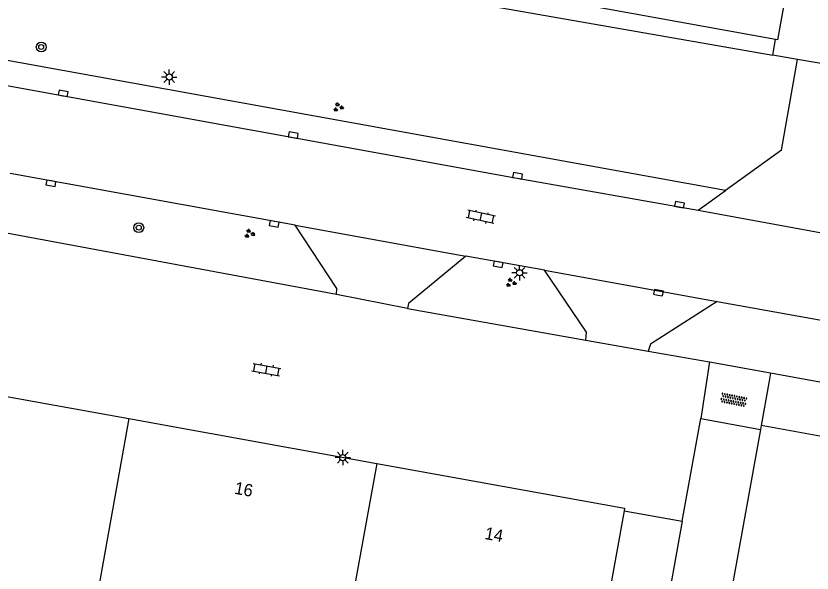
# Model space of a CAD drawing. Extents: x 130998 to 133001, y 398999 to 403002.
# Drawn here: x 132398.9 to 132463.8, y 399206.6 to 399252 of the extents above; entities that cross this region are included whole.
import ezdxf

# ---------------------------------------------------------------- set-up
doc = ezdxf.new("R2010")
doc.units = 0
for name, color, linetype in [('gg-afsc-hekwerk', 7, 'Continuous'), ('gg-anno-huisnummerreeks BGT', 7, 'Continuous'), ('gg-bbg-hoofdgebouw', 7, 'Continuous'), ('gg-bbg-tussenscheiding', 7, 'Continuous'), ('gg-knt-verharding', 7, 'Continuous'), ('gg-knt-verharding nz', 7, 'Continuous'), ('gt-symb-boom', 7, 'Continuous'), ('gt-symb-groenvak', 7, 'Continuous'), ('gt-symb-klinker verharding', 7, 'Continuous'), ('gt-symb-kolk', 7, 'Continuous'), ('gt-symb-lichtmast', 7, 'Continuous'), ('gt-symb-overige verharding', 7, 'Continuous')]:
    doc.layers.add(name, color=color, linetype=linetype)

# ---------------------------------------------------------------- blocks, each defined once
blk = doc.blocks.new('gt0-KOLK')
at = {"layer": 'gt-symb-kolk'}
blk.add_lwpolyline([(0, 0), (0.375, 0), (0.375, 0.4), (-0.375, 0.4), (-0.375, 0), (0, 0)], dxfattribs=at)
blk = doc.blocks.new('gt0-OVH')
at = {"layer": 'gt-symb-overige verharding'}
for points in [[(-0.972, 0.298), (-0.967, 0.308), (-0.965, 0.319), (-0.966, 0.33), (-0.971, 0.34), (-0.978, 0.348), (-0.988, 0.353), (-0.999, 0.355), (-1.01, 0.354), (-1.02, 0.349), (-1.028, 0.342), (-1.033, 0.332), (-1.035, 0.321), (-1.034, 0.31), (-1.029, 0.3), (-1.022, 0.292), (-1.012, 0.287), (-1.001, 0.285), (-0.99, 0.286), (-0.98, 0.291)], [(-0.872, 0.106), (-0.867, 0.116), (-0.865, 0.126), (-0.866, 0.137), (-0.871, 0.147), (-0.878, 0.156), (-0.888, 0.161), (-0.899, 0.163), (-0.91, 0.162), (-0.92, 0.157), (-0.928, 0.15), (-0.933, 0.14), (-0.935, 0.129), (-0.934, 0.118), (-0.929, 0.108), (-0.922, 0.1), (-0.912, 0.095), (-0.901, 0.092), (-0.89, 0.094), (-0.88, 0.098)], [(-0.772, 0.298), (-0.767, 0.308), (-0.765, 0.319), (-0.766, 0.33), (-0.771, 0.34), (-0.778, 0.348), (-0.788, 0.353), (-0.799, 0.355), (-0.81, 0.354), (-0.82, 0.349), (-0.828, 0.342), (-0.833, 0.332), (-0.835, 0.321), (-0.834, 0.31), (-0.829, 0.3), (-0.822, 0.292), (-0.812, 0.287), (-0.801, 0.285), (-0.79, 0.286), (-0.78, 0.291)], [(-0.672, 0.106), (-0.667, 0.116), (-0.665, 0.126), (-0.666, 0.137), (-0.671, 0.147), (-0.678, 0.156), (-0.688, 0.161), (-0.699, 0.163), (-0.71, 0.162), (-0.72, 0.157), (-0.728, 0.15), (-0.733, 0.14), (-0.735, 0.129), (-0.734, 0.118), (-0.729, 0.108), (-0.722, 0.1), (-0.712, 0.095), (-0.701, 0.092), (-0.69, 0.094), (-0.68, 0.098)], [(-0.572, 0.298), (-0.567, 0.308), (-0.565, 0.319), (-0.566, 0.33), (-0.571, 0.34), (-0.578, 0.348), (-0.588, 0.353), (-0.599, 0.355), (-0.61, 0.354), (-0.62, 0.349), (-0.628, 0.342), (-0.633, 0.332), (-0.635, 0.321), (-0.634, 0.31), (-0.629, 0.3), (-0.622, 0.292), (-0.612, 0.287), (-0.601, 0.285), (-0.59, 0.286), (-0.58, 0.291)], [(-0.472, 0.106), (-0.467, 0.116), (-0.465, 0.126), (-0.466, 0.137), (-0.471, 0.147), (-0.478, 0.156), (-0.488, 0.161), (-0.499, 0.163), (-0.51, 0.162), (-0.52, 0.157), (-0.528, 0.15), (-0.533, 0.14), (-0.535, 0.129), (-0.534, 0.118), (-0.529, 0.108), (-0.522, 0.1), (-0.512, 0.095), (-0.501, 0.092), (-0.49, 0.094), (-0.48, 0.098)], [(-0.372, 0.298), (-0.367, 0.308), (-0.365, 0.319), (-0.366, 0.33), (-0.371, 0.34), (-0.378, 0.348), (-0.388, 0.353), (-0.399, 0.355), (-0.41, 0.354), (-0.42, 0.349), (-0.428, 0.342), (-0.433, 0.332), (-0.435, 0.321), (-0.434, 0.31), (-0.429, 0.3), (-0.422, 0.292), (-0.412, 0.287), (-0.401, 0.285), (-0.39, 0.286), (-0.38, 0.291)], [(-0.272, 0.106), (-0.267, 0.116), (-0.265, 0.126), (-0.266, 0.137), (-0.271, 0.147), (-0.278, 0.156), (-0.288, 0.161), (-0.299, 0.163), (-0.31, 0.162), (-0.32, 0.157), (-0.328, 0.15), (-0.333, 0.14), (-0.335, 0.129), (-0.334, 0.118), (-0.329, 0.108), (-0.322, 0.1), (-0.312, 0.095), (-0.301, 0.092), (-0.29, 0.094), (-0.28, 0.098)], [(-0.172, 0.298), (-0.167, 0.308), (-0.165, 0.319), (-0.166, 0.33), (-0.171, 0.34), (-0.178, 0.348), (-0.188, 0.353), (-0.199, 0.355), (-0.21, 0.354), (-0.22, 0.349), (-0.228, 0.342), (-0.233, 0.332), (-0.235, 0.321), (-0.234, 0.31), (-0.229, 0.3), (-0.222, 0.292), (-0.212, 0.287), (-0.201, 0.285), (-0.19, 0.286), (-0.18, 0.291)], [(-0.072, 0.106), (-0.067, 0.116), (-0.065, 0.126), (-0.066, 0.137), (-0.071, 0.147), (-0.078, 0.156), (-0.088, 0.161), (-0.099, 0.163), (-0.11, 0.162), (-0.12, 0.157), (-0.128, 0.15), (-0.133, 0.14), (-0.135, 0.129), (-0.134, 0.118), (-0.129, 0.108), (-0.122, 0.1), (-0.112, 0.095), (-0.101, 0.092), (-0.09, 0.094), (-0.08, 0.098)], [(0.028, 0.298), (0.033, 0.308), (0.035, 0.319), (0.034, 0.33), (0.029, 0.34), (0.022, 0.348), (0.012, 0.353), (0.001, 0.355), (-0.01, 0.354), (-0.02, 0.349), (-0.028, 0.342), (-0.033, 0.332), (-0.035, 0.321), (-0.034, 0.31), (-0.029, 0.3), (-0.022, 0.292), (-0.012, 0.287), (-0.001, 0.285), (0.01, 0.286), (0.02, 0.291)], [(0.128, 0.106), (0.133, 0.116), (0.135, 0.126), (0.134, 0.137), (0.129, 0.147), (0.122, 0.156), (0.112, 0.161), (0.101, 0.163), (0.09, 0.162), (0.08, 0.157), (0.072, 0.15), (0.067, 0.14), (0.065, 0.129), (0.066, 0.118), (0.071, 0.108), (0.078, 0.1), (0.088, 0.095), (0.099, 0.092), (0.11, 0.094), (0.12, 0.098)], [(0.228, 0.298), (0.233, 0.308), (0.235, 0.319), (0.234, 0.33), (0.229, 0.34), (0.222, 0.348), (0.212, 0.353), (0.201, 0.355), (0.19, 0.354), (0.18, 0.349), (0.172, 0.342), (0.167, 0.332), (0.165, 0.321), (0.166, 0.31), (0.171, 0.3), (0.178, 0.292), (0.188, 0.287), (0.199, 0.285), (0.21, 0.286), (0.22, 0.291)], [(0.328, 0.106), (0.333, 0.116), (0.335, 0.126), (0.334, 0.137), (0.329, 0.147), (0.322, 0.156), (0.312, 0.161), (0.301, 0.163), (0.29, 0.162), (0.28, 0.157), (0.272, 0.15), (0.267, 0.14), (0.265, 0.129), (0.266, 0.118), (0.271, 0.108), (0.278, 0.1), (0.288, 0.095), (0.299, 0.092), (0.31, 0.094), (0.32, 0.098)], [(0.428, 0.298), (0.433, 0.308), (0.435, 0.319), (0.434, 0.33), (0.429, 0.34), (0.422, 0.348), (0.412, 0.353), (0.401, 0.355), (0.39, 0.354), (0.38, 0.349), (0.372, 0.342), (0.367, 0.332), (0.365, 0.321), (0.366, 0.31), (0.371, 0.3), (0.378, 0.292), (0.388, 0.287), (0.399, 0.285), (0.41, 0.286), (0.42, 0.291)], [(0.528, 0.106), (0.533, 0.116), (0.535, 0.126), (0.534, 0.137), (0.529, 0.147), (0.522, 0.156), (0.512, 0.161), (0.501, 0.163), (0.49, 0.162), (0.48, 0.157), (0.472, 0.15), (0.467, 0.14), (0.465, 0.129), (0.466, 0.118), (0.471, 0.108), (0.478, 0.1), (0.488, 0.095), (0.499, 0.092), (0.51, 0.094), (0.52, 0.098)], [(0.628, 0.298), (0.633, 0.308), (0.635, 0.319), (0.634, 0.33), (0.629, 0.34), (0.622, 0.348), (0.612, 0.353), (0.601, 0.355), (0.59, 0.354), (0.58, 0.349), (0.572, 0.342), (0.567, 0.332), (0.565, 0.321), (0.566, 0.31), (0.571, 0.3), (0.578, 0.292), (0.588, 0.287), (0.599, 0.285), (0.61, 0.286), (0.62, 0.291)], [(0.728, 0.106), (0.733, 0.116), (0.735, 0.126), (0.734, 0.137), (0.729, 0.147), (0.722, 0.156), (0.712, 0.161), (0.701, 0.163), (0.69, 0.162), (0.68, 0.157), (0.672, 0.15), (0.667, 0.14), (0.665, 0.129), (0.666, 0.118), (0.671, 0.108), (0.678, 0.1), (0.688, 0.095), (0.699, 0.092), (0.71, 0.094), (0.72, 0.098)], [(0.828, 0.298), (0.833, 0.308), (0.835, 0.319), (0.834, 0.33), (0.829, 0.34), (0.822, 0.348), (0.812, 0.353), (0.801, 0.355), (0.79, 0.354), (0.78, 0.349), (0.772, 0.342), (0.767, 0.332), (0.765, 0.321), (0.766, 0.31), (0.771, 0.3), (0.778, 0.292), (0.788, 0.287), (0.799, 0.285), (0.81, 0.286), (0.82, 0.291)], [(0.928, 0.106), (0.933, 0.116), (0.935, 0.126), (0.934, 0.137), (0.929, 0.147), (0.922, 0.156), (0.912, 0.161), (0.901, 0.163), (0.89, 0.162), (0.88, 0.157), (0.872, 0.15), (0.867, 0.14), (0.865, 0.129), (0.866, 0.118), (0.871, 0.108), (0.878, 0.1), (0.888, 0.095), (0.899, 0.092), (0.91, 0.094), (0.92, 0.098)], [(1.028, 0.298), (1.033, 0.308), (1.035, 0.319), (1.034, 0.33), (1.029, 0.34), (1.022, 0.348), (1.012, 0.353), (1.001, 0.355), (0.99, 0.354), (0.98, 0.349), (0.972, 0.342), (0.967, 0.332), (0.965, 0.321), (0.966, 0.31), (0.971, 0.3), (0.978, 0.292), (0.988, 0.287), (0.999, 0.285), (1.01, 0.286), (1.02, 0.291)], [(-0.972, -0.142), (-0.967, -0.132), (-0.965, -0.121), (-0.966, -0.11), (-0.971, -0.1), (-0.978, -0.092), (-0.988, -0.087), (-0.999, -0.085), (-1.01, -0.086), (-1.02, -0.091), (-1.028, -0.098), (-1.033, -0.108), (-1.035, -0.119), (-1.034, -0.13), (-1.029, -0.14), (-1.022, -0.148), (-1.012, -0.153), (-1.001, -0.155), (-0.99, -0.154), (-0.98, -0.149)], [(-0.872, -0.334), (-0.867, -0.324), (-0.865, -0.314), (-0.866, -0.303), (-0.871, -0.293), (-0.878, -0.284), (-0.888, -0.279), (-0.899, -0.277), (-0.91, -0.278), (-0.92, -0.283), (-0.928, -0.29), (-0.933, -0.3), (-0.935, -0.311), (-0.934, -0.322), (-0.929, -0.332), (-0.922, -0.34), (-0.912, -0.345), (-0.901, -0.348), (-0.89, -0.346), (-0.88, -0.342)], [(-0.772, -0.142), (-0.767, -0.132), (-0.765, -0.121), (-0.766, -0.11), (-0.771, -0.1), (-0.778, -0.092), (-0.788, -0.087), (-0.799, -0.085), (-0.81, -0.086), (-0.82, -0.091), (-0.828, -0.098), (-0.833, -0.108), (-0.835, -0.119), (-0.834, -0.13), (-0.829, -0.14), (-0.822, -0.148), (-0.812, -0.153), (-0.801, -0.155), (-0.79, -0.154), (-0.78, -0.149)], [(-0.672, -0.334), (-0.667, -0.324), (-0.665, -0.314), (-0.666, -0.303), (-0.671, -0.293), (-0.678, -0.284), (-0.688, -0.279), (-0.699, -0.277), (-0.71, -0.278), (-0.72, -0.283), (-0.728, -0.29), (-0.733, -0.3), (-0.735, -0.311), (-0.734, -0.322), (-0.729, -0.332), (-0.722, -0.34), (-0.712, -0.345), (-0.701, -0.348), (-0.69, -0.346), (-0.68, -0.342)], [(-0.572, -0.142), (-0.567, -0.132), (-0.565, -0.121), (-0.566, -0.11), (-0.571, -0.1), (-0.578, -0.092), (-0.588, -0.087), (-0.599, -0.085), (-0.61, -0.086), (-0.62, -0.091), (-0.628, -0.098), (-0.633, -0.108), (-0.635, -0.119), (-0.634, -0.13), (-0.629, -0.14), (-0.622, -0.148), (-0.612, -0.153), (-0.601, -0.155), (-0.59, -0.154), (-0.58, -0.149)], [(-0.472, -0.334), (-0.467, -0.324), (-0.465, -0.314), (-0.466, -0.303), (-0.471, -0.293), (-0.478, -0.284), (-0.488, -0.279), (-0.499, -0.277), (-0.51, -0.278), (-0.52, -0.283), (-0.528, -0.29), (-0.533, -0.3), (-0.535, -0.311), (-0.534, -0.322), (-0.529, -0.332), (-0.522, -0.34), (-0.512, -0.345), (-0.501, -0.348), (-0.49, -0.346), (-0.48, -0.342)], [(-0.372, -0.142), (-0.367, -0.132), (-0.365, -0.121), (-0.366, -0.11), (-0.371, -0.1), (-0.378, -0.092), (-0.388, -0.087), (-0.399, -0.085), (-0.41, -0.086), (-0.42, -0.091), (-0.428, -0.098), (-0.433, -0.108), (-0.435, -0.119), (-0.434, -0.13), (-0.429, -0.14), (-0.422, -0.148), (-0.412, -0.153), (-0.401, -0.155), (-0.39, -0.154), (-0.38, -0.149)], [(-0.272, -0.334), (-0.267, -0.324), (-0.265, -0.314), (-0.266, -0.303), (-0.271, -0.293), (-0.278, -0.284), (-0.288, -0.279), (-0.299, -0.277), (-0.31, -0.278), (-0.32, -0.283), (-0.328, -0.29), (-0.333, -0.3), (-0.335, -0.311), (-0.334, -0.322), (-0.329, -0.332), (-0.322, -0.34), (-0.312, -0.345), (-0.301, -0.348), (-0.29, -0.346), (-0.28, -0.342)], [(-0.172, -0.142), (-0.167, -0.132), (-0.165, -0.121), (-0.166, -0.11), (-0.171, -0.1), (-0.178, -0.092), (-0.188, -0.087), (-0.199, -0.085), (-0.21, -0.086), (-0.22, -0.091), (-0.228, -0.098), (-0.233, -0.108), (-0.235, -0.119), (-0.234, -0.13), (-0.229, -0.14), (-0.222, -0.148), (-0.212, -0.153), (-0.201, -0.155), (-0.19, -0.154), (-0.18, -0.149)], [(-0.072, -0.334), (-0.067, -0.324), (-0.065, -0.314), (-0.066, -0.303), (-0.071, -0.293), (-0.078, -0.284), (-0.088, -0.279), (-0.099, -0.277), (-0.11, -0.278), (-0.12, -0.283), (-0.128, -0.29), (-0.133, -0.3), (-0.135, -0.311), (-0.134, -0.322), (-0.129, -0.332), (-0.122, -0.34), (-0.112, -0.345), (-0.101, -0.348), (-0.09, -0.346), (-0.08, -0.342)], [(0.028, -0.142), (0.033, -0.132), (0.035, -0.121), (0.034, -0.11), (0.029, -0.1), (0.022, -0.092), (0.012, -0.087), (0.001, -0.085), (-0.01, -0.086), (-0.02, -0.091), (-0.028, -0.098), (-0.033, -0.108), (-0.035, -0.119), (-0.034, -0.13), (-0.029, -0.14), (-0.022, -0.148), (-0.012, -0.153), (-0.001, -0.155), (0.01, -0.154), (0.02, -0.149)], [(0.128, -0.334), (0.133, -0.324), (0.135, -0.314), (0.134, -0.303), (0.129, -0.293), (0.122, -0.284), (0.112, -0.279), (0.101, -0.277), (0.09, -0.278), (0.08, -0.283), (0.072, -0.29), (0.067, -0.3), (0.065, -0.311), (0.066, -0.322), (0.071, -0.332), (0.078, -0.34), (0.088, -0.345), (0.099, -0.348), (0.11, -0.346), (0.12, -0.342)], [(0.228, -0.142), (0.233, -0.132), (0.235, -0.121), (0.234, -0.11), (0.229, -0.1), (0.222, -0.092), (0.212, -0.087), (0.201, -0.085), (0.19, -0.086), (0.18, -0.091), (0.172, -0.098), (0.167, -0.108), (0.165, -0.119), (0.166, -0.13), (0.171, -0.14), (0.178, -0.148), (0.188, -0.153), (0.199, -0.155), (0.21, -0.154), (0.22, -0.149)], [(0.328, -0.334), (0.333, -0.324), (0.335, -0.314), (0.334, -0.303), (0.329, -0.293), (0.322, -0.284), (0.312, -0.279), (0.301, -0.277), (0.29, -0.278), (0.28, -0.283), (0.272, -0.29), (0.267, -0.3), (0.265, -0.311), (0.266, -0.322), (0.271, -0.332), (0.278, -0.34), (0.288, -0.345), (0.299, -0.348), (0.31, -0.346), (0.32, -0.342)], [(0.428, -0.142), (0.433, -0.132), (0.435, -0.121), (0.434, -0.11), (0.429, -0.1), (0.422, -0.092), (0.412, -0.087), (0.401, -0.085), (0.39, -0.086), (0.38, -0.091), (0.372, -0.098), (0.367, -0.108), (0.365, -0.119), (0.366, -0.13), (0.371, -0.14), (0.378, -0.148), (0.388, -0.153), (0.399, -0.155), (0.41, -0.154), (0.42, -0.149)], [(0.528, -0.334), (0.533, -0.324), (0.535, -0.314), (0.534, -0.303), (0.529, -0.293), (0.522, -0.284), (0.512, -0.279), (0.501, -0.277), (0.49, -0.278), (0.48, -0.283), (0.472, -0.29), (0.467, -0.3), (0.465, -0.311), (0.466, -0.322), (0.471, -0.332), (0.478, -0.34), (0.488, -0.345), (0.499, -0.348), (0.51, -0.346), (0.52, -0.342)], [(0.628, -0.142), (0.633, -0.132), (0.635, -0.121), (0.634, -0.11), (0.629, -0.1), (0.622, -0.092), (0.612, -0.087), (0.601, -0.085), (0.59, -0.086), (0.58, -0.091), (0.572, -0.098), (0.567, -0.108), (0.565, -0.119), (0.566, -0.13), (0.571, -0.14), (0.578, -0.148), (0.588, -0.153), (0.599, -0.155), (0.61, -0.154), (0.62, -0.149)], [(0.728, -0.334), (0.733, -0.324), (0.735, -0.314), (0.734, -0.303), (0.729, -0.293), (0.722, -0.284), (0.712, -0.279), (0.701, -0.277), (0.69, -0.278), (0.68, -0.283), (0.672, -0.29), (0.667, -0.3), (0.665, -0.311), (0.666, -0.322), (0.671, -0.332), (0.678, -0.34), (0.688, -0.345), (0.699, -0.348), (0.71, -0.346), (0.72, -0.342)], [(0.828, -0.142), (0.833, -0.132), (0.835, -0.121), (0.834, -0.11), (0.829, -0.1), (0.822, -0.092), (0.812, -0.087), (0.801, -0.085), (0.79, -0.086), (0.78, -0.091), (0.772, -0.098), (0.767, -0.108), (0.765, -0.119), (0.766, -0.13), (0.771, -0.14), (0.778, -0.148), (0.788, -0.153), (0.799, -0.155), (0.81, -0.154), (0.82, -0.149)], [(0.928, -0.334), (0.933, -0.324), (0.935, -0.314), (0.934, -0.303), (0.929, -0.293), (0.922, -0.284), (0.912, -0.279), (0.901, -0.277), (0.89, -0.278), (0.88, -0.283), (0.872, -0.29), (0.867, -0.3), (0.865, -0.311), (0.866, -0.322), (0.871, -0.332), (0.878, -0.34), (0.888, -0.345), (0.899, -0.348), (0.91, -0.346), (0.92, -0.342)], [(1.028, -0.142), (1.033, -0.132), (1.035, -0.121), (1.034, -0.11), (1.029, -0.1), (1.022, -0.092), (1.012, -0.087), (1.001, -0.085), (0.99, -0.086), (0.98, -0.091), (0.972, -0.098), (0.967, -0.108), (0.965, -0.119), (0.966, -0.13), (0.971, -0.14), (0.978, -0.148), (0.988, -0.153), (0.999, -0.155), (1.01, -0.154), (1.02, -0.149)]]:
    blk.add_lwpolyline(points, close=True, dxfattribs=at)
blk = doc.blocks.new('gt0-BOOM')
at = {"layer": 'gt-symb-boom'}
for radius in [0.4, 0.2]:
    blk.add_circle((0, 0), radius, dxfattribs=at)
blk = doc.blocks.new('gt0-LMAST')
at = {"layer": 'gt-symb-lichtmast'}
for p, q in [((-0.182, 0.173), (-0.447, 0.438)), ((-0.005, 0.246), (-0.005, 0.621)), ((0.172, 0.173), (0.437, 0.438)), ((-0.255, -0.004), (-0.63, -0.004)), ((-0.182, -0.181), (-0.447, -0.446)), ((-0.005, -0.254), (-0.005, -0.629)), ((0.437, -0.446), (0.172, -0.181)), ((0.245, -0.004), (0.62, -0.004))]:
    blk.add_line(p, q, dxfattribs=at)
blk.add_circle((-0.005, -0.004), 0.25, dxfattribs=at)
blk = doc.blocks.new('gt0-GRVAK')
at = {"layer": 'gt-symb-groenvak'}
for p, q in [((-0.11, 0.189), (-0.228, 0.24)), ((-0.182, 0.153), (0.088, 0.153)), ((-0.091, 0.211), (-0.156, 0.322)), ((-0.047, 0.214), (-0.047, 0.393)), ((-0.004, 0.211), (0.061, 0.322)), ((0.015, 0.189), (0.133, 0.24)), ((0.262, -0.052), (0.197, 0.059)), ((0.305, -0.049), (0.305, 0.13)), ((0.349, -0.052), (0.414, 0.059)), ((-0.245, -0.228), (-0.363, -0.177)), ((-0.318, -0.264), (-0.047, -0.264)), ((-0.226, -0.206), (-0.291, -0.095)), ((-0.183, -0.203), (-0.183, -0.024)), ((-0.139, -0.206), (-0.074, -0.095)), ((-0.12, -0.228), (-0.002, -0.177)), ((0.243, -0.074), (0.125, -0.023)), ((0.17, -0.11), (0.441, -0.11)), ((0.368, -0.074), (0.486, -0.023))]:
    blk.add_line(p, q, dxfattribs=at)
blk = doc.blocks.new('gt0-KL1')
at = {"layer": 'gt-symb-klinker verharding'}
for p, q in [((-1.15, 0.3), (1.15, 0.3)), ((-1, -0.3), (-1, 0.3)), ((-0.5, 0.3), (-0.5, 0.45)), ((0, -0.3), (0, 0.3)), ((0.5, 0.3), (0.5, 0.45)), ((1, -0.3), (1, 0.3)), ((-1.15, -0.3), (1.15, -0.3)), ((-0.5, -0.45), (-0.5, -0.3)), ((0.5, -0.45), (0.5, -0.3))]:
    blk.add_line(p, q, dxfattribs=at)

msp = doc.modelspace()

# ---------------------------------------------------------------- linework, layer by layer
at = {"layer": 'gg-afsc-hekwerk'}
for p, q in [((132460.601, 399248.82), (132460.809, 399250.107)), ((132462.598, 399248.474), (132460.601, 399248.82)), ((132468.473, 399247.458), (132462.598, 399248.474)), ((132455.426, 399223.831), (132454.727, 399219.227)), ((132453.207, 399210.854), (132454.727, 399219.227)), ((132454.727, 399219.227), (132459.591, 399218.314)), ((132448.481, 399211.712), (132453.207, 399210.854)), ((132453.207, 399210.854), (132451.577, 399201.878))]:
    msp.add_line(p, q, dxfattribs=at)
at = {"layer": 'gg-bbg-hoofdgebouw'}
for p, q in [((132387.901, 399222.87), (132408.103, 399219.217)), ((132408.103, 399219.217), (132428.306, 399215.564)), ((132459.591, 399218.314), (132453.594, 399185.159)), ((132459.65, 399218.642), (132459.591, 399218.314)), ((132514.6, 399208.747), (132459.65, 399218.642)), ((132428.306, 399215.564), (132448.517, 399211.909)), ((132448.481, 399211.712), (132444.01, 399186.885)), ((132448.517, 399211.909), (132448.481, 399211.712))]:
    msp.add_line(p, q, dxfattribs=at)
for points in [[(132413.478, 399310.379), (132413.991, 399313.232), (132414.422, 399315.091), (132470.77, 399304.908), (132470.429, 399303.025), (132470.54, 399303.004), (132460.978, 399250.076), (132460.809, 399250.107)], [(132460.809, 399250.107), (132404.38, 399260.315), (132404.401, 399260.417)]]:
    msp.add_lwpolyline(points, dxfattribs=at)
at = {"layer": 'gg-bbg-tussenscheiding'}
for p, q in [((132408.103, 399219.217), (132399.369, 399170.915)), ((132428.306, 399215.564), (132419.572, 399167.262))]:
    msp.add_line(p, q, dxfattribs=at)
at = {"layer": 'gg-knt-verharding'}
for p, q in [((132404.069, 399258.766), (132460.601, 399248.82)), ((132461.308, 399241.073), (132462.598, 399248.474)), ((132461.308, 399241.073), (132456.746, 399237.79)), ((132421.656, 399234.98), (132398.405, 399239.184)), ((132425.026, 399229.316), (132395.042, 399234.894)), ((132441.986, 399231.293), (132435.556, 399232.447)), ((132430.822, 399228.19), (132425.026, 399229.316)), ((132430.822, 399228.19), (132445.347, 399225.613)), ((132445.347, 399225.613), (132450.424, 399224.716)), ((132450.424, 399224.716), (132455.426, 399223.831)), ((132455.426, 399223.831), (132460.42, 399222.935)), ((132460.42, 399222.935), (132460.277, 399222.139)), ((132460.42, 399222.935), (132515.289, 399213.088)), ((132460.277, 399222.139), (132459.65, 399218.642))]:
    msp.add_line(p, q, dxfattribs=at)
for points in [[(132456.746, 399237.79), (132384.033, 399250.95), (132383.627, 399248.942)], [(132425.026, 399229.316), (132425.063, 399229.816), (132421.656, 399234.98)], [(132435.556, 399232.447), (132430.898, 399228.596), (132430.822, 399228.19)], [(132445.347, 399225.613), (132445.415, 399226.249), (132441.986, 399231.293)], [(132456.05, 399228.766), (132450.61, 399225.289), (132450.424, 399224.716)], [(132456.05, 399228.766), (132466.524, 399226.871), (132480.682, 399224.506), (132496.024, 399221.539), (132511.888, 399218.7)]]:
    msp.add_lwpolyline(points, dxfattribs=at)
at = {"layer": 'gg-knt-verharding nz'}
for p, q in [((132454.521, 399236.182), (132456.746, 399237.79)), ((132454.521, 399236.182), (132471.991, 399232.987)), ((132421.656, 399234.98), (132435.556, 399232.447)), ((132441.986, 399231.293), (132456.05, 399228.766))]:
    msp.add_line(p, q, dxfattribs=at)
msp.add_lwpolyline([(132383.627, 399248.942), (132385.109, 399248.703), (132439.752, 399238.796), (132454.521, 399236.182)], dxfattribs=at)

# ---------------------------------------------------------------- block references
at = {"layer": 'gt-symb-boom'}
for p in [(132400.948, 399249.483), (132408.902, 399234.774)]:
    msp.add_blockref('gt0-BOOM', p, dxfattribs=at)
at = {"layer": 'gt-symb-groenvak'}
for p in [(132425.164, 399244.579), (132417.912, 399234.279), (132439.237, 399230.283)]:
    msp.add_blockref('gt0-GRVAK', p, dxfattribs=at)
at = {"layer": 'gt-symb-klinker verharding'}
for p, rotation in [((132436.786, 399235.651), 167.589225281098), ((132419.31, 399223.209), -10.25359802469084)]:
    msp.add_blockref('gt0-KL1', p, dxfattribs=dict(at, rotation=rotation))
at = {"layer": 'gt-symb-kolk'}
for p, rotation in [((132402.708, 399245.513), -10.197205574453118), ((132421.464, 399242.113), -10.25359802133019), ((132439.752, 399238.796), -10.253598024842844), ((132401.78, 399238.573), 169.51061019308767), ((132452.95, 399236.448), -10.197205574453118), ((132419.981, 399235.283), 169.45426563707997), ((132438.235, 399231.984), 169.56697526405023), ((132451.229, 399229.279), -11.186329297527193)]:
    msp.add_blockref('gt0-KOLK', p, dxfattribs=dict(at, rotation=rotation))
at = {"layer": 'gt-symb-lichtmast'}
for p in [(132411.388, 399247.043), (132439.954, 399231.095), (132425.54, 399216.04)]:
    msp.add_blockref('gt0-LMAST', p, dxfattribs=at)
at = {"layer": 'gt-symb-overige verharding', "rotation": -11.298700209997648}
msp.add_blockref('gt0-OVH', (132457.406, 399220.736), dxfattribs=at)

# ---------------------------------------------------------------- texts
at = {"layer": 'gg-anno-huisnummerreeks BGT'}
for s, p in [('16', (132416.647, 399213.1)), ('14', (132437.05, 399209.41))]:
    msp.add_text(s, height=1, rotation=349.7, dxfattribs=at).set_placement(p)

doc.saveas('drawing.dxf')
